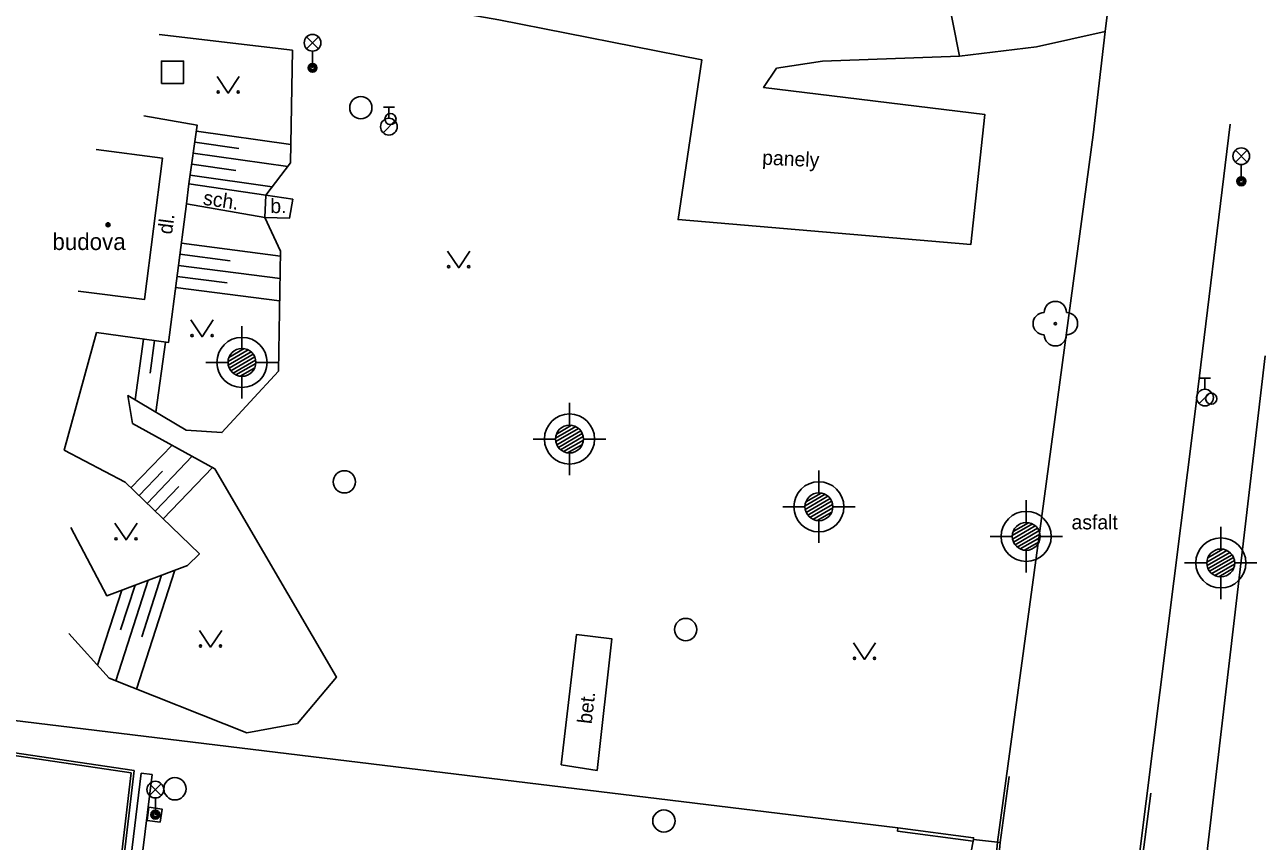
# Model space of a CAD drawing. Extents: x -540235 to -537963, y -1184915 to -1183660.
# Drawn here: x -540131 to -540075.6, y -1184001.9 to -1183965.3 of the extents above; entities that cross this region are included whole.
import ezdxf

# ---------------------------------------------------------------- set-up
doc = ezdxf.new("R2010")
doc.units = 0
for name, color, linetype in [('Vrstva 10', 7, 'Continuous'), ('Vrstva 11', 7, 'Continuous'), ('Vrstva 14', 7, 'Continuous'), ('Vrstva 15', 7, 'Continuous'), ('Vrstva 22', 7, 'Continuous'), ('Vrstva 26', 7, 'Continuous'), ('Vrstva 27', 7, 'Continuous'), ('Vrstva 28', 7, 'Continuous'), ('Vrstva 33', 7, 'Continuous'), ('Vrstva 35', 7, 'Continuous'), ('Vrstva 36', 7, 'Continuous'), ('Vrstva 39', 7, 'Continuous'), ('Vrstva 40', 7, 'Continuous'), ('Vrstva 41', 7, 'Continuous'), ('Vrstva 5', 7, 'Continuous'), ('Vrstva 7', 7, 'Continuous'), ('Vrstva 8', 7, 'Continuous')]:
    doc.layers.add(name, color=color, linetype=linetype)

msp = doc.modelspace()

# ---------------------------------------------------------------- linework, layer by layer
at = {"layer": 'Vrstva 10'}
for p, q in [((-540078.46, -1183982.89), (-540080.947, -1184002.636)), ((-540126.08, -1183998.755), (-540131.95, -1183997.885)), ((-540129.3, -1184026.075), (-540126.08, -1183998.755))]:
    msp.add_line(p, q, dxfattribs=at)
for points in [[(-540082.04, -1183962.04), (-540082.48, -1183965.59)], [(-540082.48, -1183965.59), (-540083.01, -1183970.23), (-540085.41, -1183988)], [(-540078.46, -1183982.89), (-540076.86, -1183969.75)], [(-540085.41, -1183988), (-540087.303, -1184001.976), (-540087.61, -1184005.175)]]:
    msp.add_lwpolyline(points, dxfattribs=at)
at = {"layer": 'Vrstva 11'}
for p, q in [((-540126.213, -1183998.856), (-540131.965, -1183998.004)), ((-540129.419, -1184026.061), (-540126.213, -1183998.856)), ((-540129.092, -1184026.105), (-540125.768, -1183998.87)), ((-540125.768, -1183998.87), (-540125.272, -1183998.93)), ((-540125.272, -1183998.93), (-540128.597, -1184026.175)), ((-540080.428, -1183999.778), (-540080.798, -1184002.655))]:
    msp.add_line(p, q, dxfattribs=at)
for points in [[(-540089.02, -1183966.69), (-540095.17, -1183966.92), (-540097.23, -1183967.24), (-540097.81, -1183968.1), (-540087.88, -1183969.31), (-540088.51, -1183975.15), (-540101.65, -1183974.03), (-540100.59, -1183966.86), (-540109.71, -1183965.07), (-540124.55, -1183962.46)], [(-540089.6, -1183963.73), (-540089.02, -1183966.69)], [(-540089.02, -1183966.69), (-540085.56, -1183966.28), (-540082.48, -1183965.59)], [(-540125.64, -1183969.38), (-540123.25, -1183969.8), (-540123.62, -1183972.43)], [(-540123.73, -1183973.33), (-540123.62, -1183972.43)], [(-540123.62, -1183972.43), (-540120.17, -1183972.93)], [(-540123.73, -1183973.33), (-540124.54, -1183979.55), (-540127.77, -1183979.1)], [(-540120.21, -1183973.93), (-540123.73, -1183973.33)], [(-540120.17, -1183972.93), (-540118.96, -1183973.12), (-540119.11, -1183973.97), (-540120.21, -1183973.93)], [(-540120.17, -1183972.93), (-540120.21, -1183973.93)], [(-540086.777, -1183999.027), (-540087.183, -1184001.991), (-540087.491, -1184005.188)], [(-540124.907, -1184001.08), (-540125.501, -1184000.998), (-540125.419, -1184000.403), (-540124.825, -1184000.485), (-540124.907, -1184001.08)], [(-540088.4, -1184001.925), (-540088.98, -1184004.955), (-540088.203, -1184005.08), (-540087.709, -1184005.159), (-540087.61, -1184005.175)]]:
    msp.add_lwpolyline(points, dxfattribs=at)
at = {"layer": 'Vrstva 14'}
for points in [[(-540124.96, -1183965.73), (-540118.97, -1183966.43), (-540119.06, -1183971.49), (-540120.17, -1183972.93)], [(-540120.21, -1183973.93), (-540119.51, -1183975.45), (-540119.6, -1183980.84), (-540122.14, -1183983.59), (-540123.74, -1183983.48), (-540126.36, -1183981.93), (-540126.15, -1183983.18), (-540122.46, -1183985.21), (-540117, -1183994.57), (-540118.75, -1183996.65), (-540121.02, -1183997.06), (-540127.21, -1183994.61), (-540129.02, -1183992.6)], [(-540127.77, -1183979.1), (-540129.22, -1183984.38), (-540126.49, -1183985.82), (-540123.15, -1183989.03), (-540123.68, -1183989.55), (-540127.31, -1183990.91), (-540128.93, -1183987.85)]]:
    msp.add_lwpolyline(points, dxfattribs=at)
at = {"layer": 'Vrstva 15'}
for p, q in [((-540123.2866, -1183970.0602), (-540119.0452, -1183970.6569)), ((-540123.3563, -1183970.5553), (-540121.3748, -1183970.8341)), ((-540123.4259, -1183971.0504), (-540119.1814, -1183971.6475)), ((-540123.4956, -1183971.5455), (-540121.5141, -1183971.8243)), ((-540123.5652, -1183972.0407), (-540119.8837, -1183972.5586)), ((-540124.024, -1183975.5876), (-540121.773, -1183975.8808)), ((-540123.9594, -1183975.0918), (-540119.5137, -1183975.6708)), ((-540124.0886, -1183976.0835), (-540119.5305, -1183976.677)), ((-540124.1531, -1183976.5793), (-540121.9022, -1183976.8724)), ((-540124.2177, -1183977.0751), (-540119.5473, -1183977.6833)), ((-540125.6605, -1183979.3939), (-540126.0402, -1183982.1192)), ((-540125.1653, -1183979.4629), (-540125.3695, -1183980.929)), ((-540124.67, -1183979.5319), (-540125.1074, -1183982.671)), ((-540126.225, -1183986.0747), (-540124.3792, -1183984.1542)), ((-540125.504, -1183986.7676), (-540123.472, -1183984.6533)), ((-540125.8645, -1183986.4212), (-540124.8019, -1183985.3155)), ((-540124.783, -1183987.4606), (-540122.5647, -1183985.1524)), ((-540125.1435, -1183987.1141), (-540124.0809, -1183986.0085)), ((-540124.2486, -1183989.763), (-540125.9762, -1183995.0983)), ((-540124.8468, -1183989.9871), (-540125.7431, -1183992.7552)), ((-540125.4449, -1183990.2112), (-540126.908, -1183994.7296)), ((-540126.043, -1183990.4353), (-540126.6945, -1183992.4472)), ((-540126.6411, -1183990.6594), (-540127.7325, -1183994.0298))]:
    msp.add_line(p, q, dxfattribs=at)
at = {"layer": 'Vrstva 22'}
msp.add_circle((-540084.71, -1183978.7), 0.05, dxfattribs=at)
for centre, start, end in [((-540084.71, -1183978.2), 0, 180), ((-540085.21, -1183978.7), 90, 270), ((-540084.21, -1183978.7), 270, 90), ((-540084.71, -1183979.2), 180, 0)]:
    msp.add_arc(centre, 0.5, start, end, dxfattribs=at)
at = {"layer": 'Vrstva 26'}
msp.add_lwpolyline([(-540124.86, -1183967.92), (-540123.86, -1183967.92), (-540123.86, -1183966.92), (-540124.86, -1183966.92)], close=True, dxfattribs=at)
at = {"layer": 'Vrstva 27'}
for centre in [(-540115.9, -1183969.01), (-540116.64, -1183985.8), (-540101.31, -1183992.43), (-540124.251, -1183999.576), (-540102.29, -1184001.02)]:
    msp.add_circle(centre, 0.5, dxfattribs=at)
at = {"layer": 'Vrstva 28'}
for p, q in [((-540114.89, -1183968.985), (-540114.39, -1183968.985)), ((-540114.64, -1183969.485), (-540114.64, -1183968.985)), ((-540114.898, -1183970.132), (-540114.368, -1183969.602)), ((-540078.24, -1183981.145), (-540077.74, -1183981.145)), ((-540077.99, -1183981.645), (-540077.99, -1183981.145)), ((-540078.248, -1183982.292), (-540077.718, -1183981.762))]:
    msp.add_line(p, q, dxfattribs=at)
for centre, radius in [((-540114.64, -1183969.86), 0.375), ((-540114.57, -1183969.52), 0.25), ((-540077.99, -1183982.02), 0.375), ((-540077.71, -1183982.07), 0.25)]:
    msp.add_circle(centre, radius, dxfattribs=at)
at = {"layer": 'Vrstva 33'}
for p, q in [((-540118.335, -1183966.36), (-540117.805, -1183965.83)), ((-540118.335, -1183965.83), (-540117.805, -1183966.36)), ((-540118.07, -1183966.47), (-540118.07, -1183967.22)), ((-540076.625, -1183971.45), (-540076.095, -1183970.92)), ((-540076.625, -1183970.92), (-540076.095, -1183971.45)), ((-540076.36, -1183971.56), (-540076.36, -1183972.31)), ((-540125.395, -1183999.88), (-540124.865, -1183999.35)), ((-540125.395, -1183999.35), (-540124.865, -1183999.88)), ((-540125.13, -1183999.99), (-540125.13, -1184000.74))]:
    msp.add_line(p, q, dxfattribs=at)
for centre, radius in [((-540118.07, -1183966.095), 0.375), ((-540118.07, -1183967.22), 0.2), ((-540118.07, -1183967.22), 0.1445), ((-540118.07, -1183967.22), 0.0876), ((-540076.36, -1183971.185), 0.375), ((-540076.36, -1183972.31), 0.2), ((-540076.36, -1183972.31), 0.1445), ((-540076.36, -1183972.31), 0.0876), ((-540125.13, -1183999.615), 0.375), ((-540125.13, -1184000.74), 0.2), ((-540125.13, -1184000.74), 0.1445), ((-540125.13, -1184000.74), 0.0876)]:
    msp.add_circle(centre, radius, dxfattribs=at)
at = {"layer": 'Vrstva 35'}
for p, q in [((-540121.24, -1183979.815), (-540121.24, -1183978.815)), ((-540121.863, -1183980.401), (-540120.962, -1183979.881)), ((-540121.853, -1183980.557), (-540120.832, -1183979.967)), ((-540121.822, -1183980.216), (-540121.143, -1183979.823)), ((-540121.865, -1183980.44), (-540122.865, -1183980.44)), ((-540121.811, -1183980.694), (-540120.734, -1183980.072)), ((-540121.74, -1183980.815), (-540120.666, -1183980.194)), ((-540121.64, -1183980.919), (-540120.625, -1183980.333)), ((-540121.508, -1183981.004), (-540120.618, -1183980.49)), ((-540120.615, -1183980.44), (-540119.615, -1183980.44)), ((-540121.323, -1183981.059), (-540120.663, -1183980.678)), ((-540121.24, -1183981.065), (-540121.24, -1183982.065)), ((-540106.53, -1183983.255), (-540106.53, -1183982.255)), ((-540107.153, -1183983.841), (-540106.252, -1183983.321)), ((-540107.112, -1183983.656), (-540106.433, -1183983.263)), ((-540107.155, -1183983.88), (-540108.155, -1183983.88)), ((-540107.143, -1183983.997), (-540106.122, -1183983.407)), ((-540107.101, -1183984.134), (-540106.024, -1183983.512)), ((-540107.03, -1183984.255), (-540105.956, -1183983.634)), ((-540106.93, -1183984.359), (-540105.915, -1183983.773)), ((-540106.798, -1183984.444), (-540105.908, -1183983.93)), ((-540105.905, -1183983.88), (-540104.905, -1183983.88)), ((-540106.613, -1183984.499), (-540105.953, -1183984.118)), ((-540106.53, -1183984.505), (-540106.53, -1183985.505)), ((-540095.33, -1183986.295), (-540095.33, -1183985.295)), ((-540095.953, -1183986.881), (-540095.052, -1183986.361)), ((-540095.943, -1183987.037), (-540094.922, -1183986.447)), ((-540095.912, -1183986.696), (-540095.233, -1183986.303)), ((-540095.901, -1183987.174), (-540094.824, -1183986.552)), ((-540095.83, -1183987.295), (-540094.756, -1183986.674)), ((-540086.02, -1183987.625), (-540086.02, -1183986.625)), ((-540095.955, -1183986.92), (-540096.955, -1183986.92)), ((-540095.73, -1183987.399), (-540094.715, -1183986.813)), ((-540095.598, -1183987.484), (-540094.708, -1183986.97)), ((-540095.413, -1183987.539), (-540094.753, -1183987.158)), ((-540094.705, -1183986.92), (-540093.705, -1183986.92)), ((-540095.33, -1183987.545), (-540095.33, -1183988.545)), ((-540086.643, -1183988.211), (-540085.742, -1183987.691)), ((-540086.633, -1183988.367), (-540085.612, -1183987.777)), ((-540086.602, -1183988.026), (-540085.923, -1183987.633)), ((-540077.28, -1183988.815), (-540077.28, -1183987.815)), ((-540086.645, -1183988.25), (-540087.645, -1183988.25)), ((-540086.591, -1183988.504), (-540085.514, -1183987.882)), ((-540086.52, -1183988.625), (-540085.446, -1183988.004)), ((-540086.42, -1183988.729), (-540085.405, -1183988.143)), ((-540086.288, -1183988.814), (-540085.398, -1183988.3)), ((-540085.395, -1183988.25), (-540084.395, -1183988.25)), ((-540086.103, -1183988.869), (-540085.443, -1183988.488)), ((-540086.02, -1183988.875), (-540086.02, -1183989.875)), ((-540077.903, -1183989.401), (-540077.002, -1183988.881)), ((-540077.862, -1183989.216), (-540077.183, -1183988.823)), ((-540077.905, -1183989.44), (-540078.905, -1183989.44)), ((-540077.893, -1183989.557), (-540076.872, -1183988.967)), ((-540077.851, -1183989.694), (-540076.774, -1183989.072)), ((-540077.78, -1183989.815), (-540076.706, -1183989.194)), ((-540077.68, -1183989.919), (-540076.665, -1183989.333)), ((-540076.655, -1183989.44), (-540075.655, -1183989.44)), ((-540077.548, -1183990.004), (-540076.658, -1183989.49)), ((-540077.363, -1183990.059), (-540076.703, -1183989.678)), ((-540077.28, -1183990.065), (-540077.28, -1183991.065))]:
    msp.add_line(p, q, dxfattribs=at)
for centre, radius in [((-540121.24, -1183980.44), 1.125), ((-540121.24, -1183980.44), 0.625), ((-540106.53, -1183983.88), 1.125), ((-540106.53, -1183983.88), 0.625), ((-540095.33, -1183986.92), 1.125), ((-540095.33, -1183986.92), 0.625), ((-540086.02, -1183988.25), 1.125), ((-540086.02, -1183988.25), 0.625), ((-540077.28, -1183989.44), 1.125), ((-540077.28, -1183989.44), 0.625)]:
    msp.add_circle(centre, radius, dxfattribs=at)
at = {"layer": 'Vrstva 36'}
for points in [[(-540122.3586, -1183967.6013), (-540121.8586, -1183968.3513), (-540121.3586, -1183967.6013)], [(-540112.0069, -1183975.4416), (-540111.5069, -1183976.1916), (-540111.0069, -1183975.4416)], [(-540123.5284, -1183978.5351), (-540123.0284, -1183979.2851), (-540122.5284, -1183978.5351)], [(-540126.9436, -1183987.6587), (-540126.4436, -1183988.4087), (-540125.9436, -1183987.6587)], [(-540123.151, -1183992.4701), (-540122.651, -1183993.2201), (-540122.151, -1183992.4701)], [(-540093.7799, -1183993.0208), (-540093.2799, -1183993.7708), (-540092.7799, -1183993.0208)]]:
    msp.add_lwpolyline(points, dxfattribs=at)
for centre in [(-540122.3088, -1183968.3011), (-540121.4094, -1183968.3011), (-540111.9571, -1183976.1414), (-540111.0577, -1183976.1414), (-540123.4786, -1183979.2349), (-540122.5792, -1183979.2349), (-540126.8938, -1183988.3585), (-540125.9944, -1183988.3585), (-540123.1012, -1183993.1699), (-540122.2018, -1183993.1699), (-540093.7301, -1183993.7206), (-540092.8307, -1183993.7206)]:
    msp.add_circle(centre, 0.05, dxfattribs=at)
at = {"layer": 'Vrstva 39'}
for radius in [0.09, 0.0398]:
    msp.add_circle((-540127.2537, -1183974.2641), radius, dxfattribs=at)
at = {"layer": 'Vrstva 5'}
msp.add_lwpolyline([(-540127.7859, -1183970.8904), (-540124.81, -1183971.27), (-540125.62, -1183977.62), (-540128.5959, -1183977.2404)], dxfattribs=at)
at = {"layer": 'Vrstva 7'}
for p, q in [((-540077.971, -1184003.016), (-540075.28, -1183980.14)), ((-540132.071, -1183996.433), (-540091.78, -1184001.326)), ((-540088.4, -1184001.925), (-540091.8, -1184001.475))]:
    msp.add_line(p, q, dxfattribs=at)
for points in [[(-540106.91, -1183998.5), (-540105.29, -1183998.75), (-540104.63, -1183992.84), (-540106.21, -1183992.65), (-540106.91, -1183998.5)], [(-540091.8, -1184001.475), (-540091.78, -1184001.326), (-540088.38, -1184001.776), (-540088.39, -1184001.85), (-540088.4, -1184001.925)]]:
    msp.add_lwpolyline(points, dxfattribs=at)
at = {"layer": 'Vrstva 8'}
msp.add_lwpolyline([(-540087.183, -1184001.991), (-540087.303, -1184001.976), (-540088.39, -1184001.85)], dxfattribs=at)

# ---------------------------------------------------------------- texts
at = {"layer": 'Vrstva 40'}
for s, rotation, p in [('panely', 357.35724, (-540097.886, -1183971.563)), ('sch.', 351.46173, (-540123.013, -1183973.359)), ('dl.', 82.75073, (-540124.38, -1183974.715)), ('bet.', 83.3839, (-540105.535, -1183996.687))]:
    msp.add_text(s, height=0.65, rotation=rotation, dxfattribs=at).set_placement(p)
for s, p in [('b.', (-540119.965, -1183973.741)), ('asfalt', (-540083.983, -1183987.935))]:
    msp.add_text(s, height=0.65, dxfattribs=at).set_placement(p)
at = {"layer": 'Vrstva 41'}
msp.add_text('budova', height=0.75, dxfattribs=at).set_placement((-540129.753, -1183975.396))

doc.saveas('drawing.dxf')
